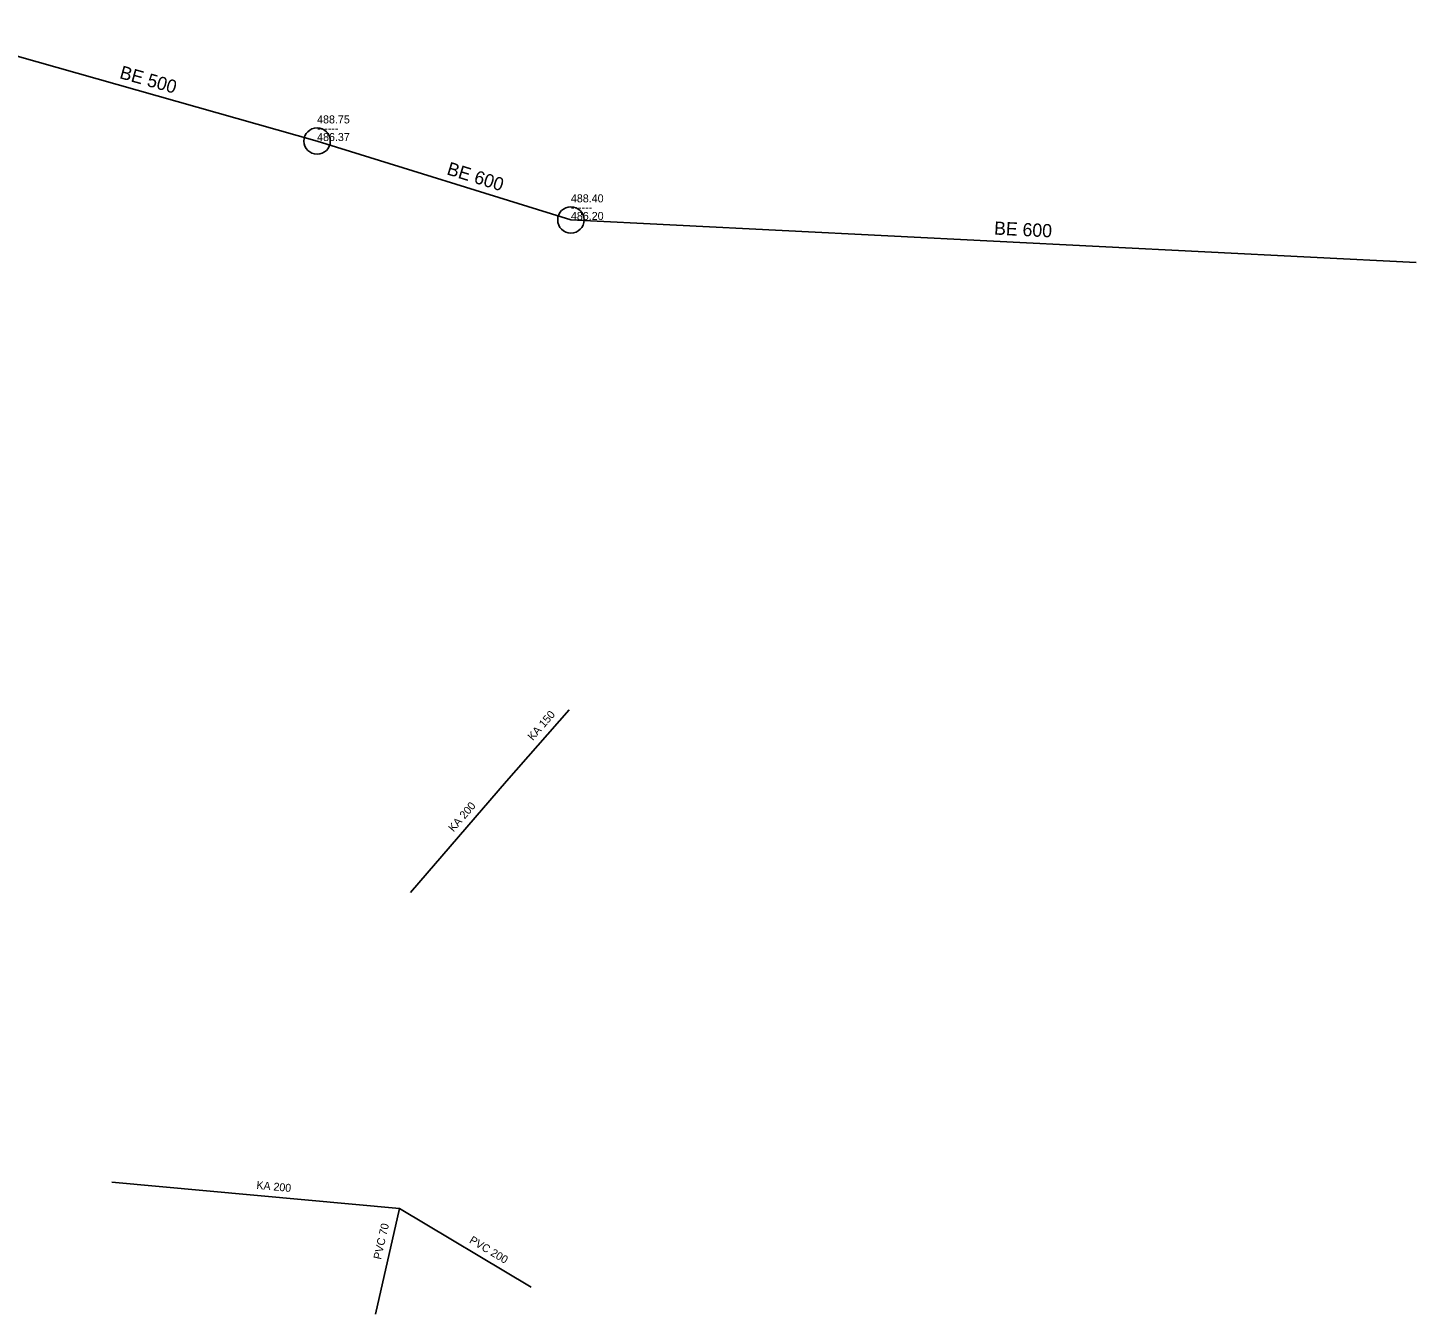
# Model space of a CAD drawing. Extents: x -770228 to -769930, y -1182222 to -1181927.
# Drawn here: x -770036.7 to -769984.1, y -1182221.8 to -1182173.1 of the extents above; entities that cross this region are included whole.
import ezdxf

# ---------------------------------------------------------------- set-up
doc = ezdxf.new("R2010")
doc.units = 0
for name, color, linetype in [('Kanalizační přípojky', 7, 'Continuous'), ('Kanalizační stoka', 7, 'Continuous'), ('Kanalizační šachty', 7, 'Continuous'), ('Popis', 7, 'Continuous')]:
    doc.layers.add(name, color=color, linetype=linetype)

msp = doc.modelspace()

# ---------------------------------------------------------------- linework, layer by layer
at = {"layer": 'Kanalizační přípojky'}
for points in [[(-770016.19, -1182198.89), (-770018.56, -1182201.6)], [(-770018.56, -1182201.6), (-770022.2, -1182205.81)], [(-770022.62, -1182217.79), (-770033.52, -1182216.79)], [(-770023.53, -1182221.79), (-770022.62, -1182217.79)], [(-770017.63, -1182220.77), (-770022.62, -1182217.79)]]:
    msp.add_lwpolyline(points, dxfattribs=at)
at = {"layer": 'Kanalizační stoka'}
for points in [[(-770040.91, -1182173.06), (-770025.74, -1182177.35)], [(-770025.74, -1182177.35), (-770016.12, -1182180.34)], [(-770016.12, -1182180.34), (-769984.08, -1182181.945)]]:
    msp.add_lwpolyline(points, dxfattribs=at)
at = {"layer": 'Kanalizační šachty'}
for centre in [(-770025.74, -1182177.35), (-770016.12, -1182180.34)]:
    msp.add_circle(centre, 0.5, dxfattribs=at)

# ---------------------------------------------------------------- texts
at = {"layer": 'Popis'}
for s, height, rotation, p in [('BE 500', 0.5, 344.2094, (-770033.257, -1182174.964)), ('488.75', 0.303, 360, (-770025.74, -1182176.683)), ('486.37', 0.303, 360, (-770025.74, -1182177.35)), ('------', 0.303, 360, (-770025.74, -1182177.017)), ('BE 600', 0.5, 342.7342, (-770020.856, -1182178.606)), ('488.40', 0.303, 360, (-770016.12, -1182179.673)), ('486.20', 0.303, 360, (-770016.12, -1182180.34)), ('------', 0.303, 360, (-770016.12, -1182180.007)), ('BE 600', 0.5, 357.1326, (-770000.088, -1182180.893)), ('KA 150', 0.3, 48.829, (-770017.563, -1182200.08)), ('KA 200', 0.3, 49.153, (-770020.569, -1182203.541)), ('KA 200', 0.3, 354.7582, (-770028.047, -1182217.041)), ('PVC 70', 0.3, 77.1834, (-770023.319, -1182219.735)), ('PVC 200', 0.3, 329.1546, (-770019.997, -1182219.065))]:
    msp.add_text(s, height=height, rotation=rotation, dxfattribs=at).set_placement(p)

doc.saveas('drawing.dxf')
